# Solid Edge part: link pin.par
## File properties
Author: Vicky Raina
Template: Normal.par
Last saved by: Robert a Rhodes jr
Revision: 5
Application: Solid Edge
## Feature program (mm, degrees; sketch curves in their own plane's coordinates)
sketch for "unnamed RevolvedProtrusion 1" plane through (0, 0, 0) normal (0, -1, 0) x-axis (1, 0, 0)
  line (0, 27.2464) -> (7.5, 27.2464)
  line (7.5, 27.2464) -> (7.5, 20.2464)
  line (7.5, 20.2464) -> (5, 20.2464)
  line (5, 20.2464) -> (5, -22.7536)
  line (5, -22.7536) -> (0, -22.7536)
  line (0, -22.7536) -> (0, 27.2464)
revolve "unnamed RevolvedProtrusion 1" add finite 360 deg
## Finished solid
Body 1: solid body, 5 faces, 4 edges, 0 vertices.
  Faces by surface: plane 3, cylinder 2
  Edges by curve: circle 4
Bounding box of the edges (mm): 15.000 x 15.000 x 50.000, from (-7.5, -7.5, -22.7536) to (7.5, 7.5, 27.2464).
Cylindrical faces by radius (mm): R5 x1, R7.5 x1
Planar faces by outward normal: +z 1, -z 2
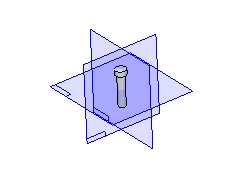
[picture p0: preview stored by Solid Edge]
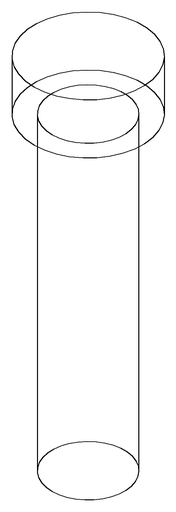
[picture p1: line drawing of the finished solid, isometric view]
